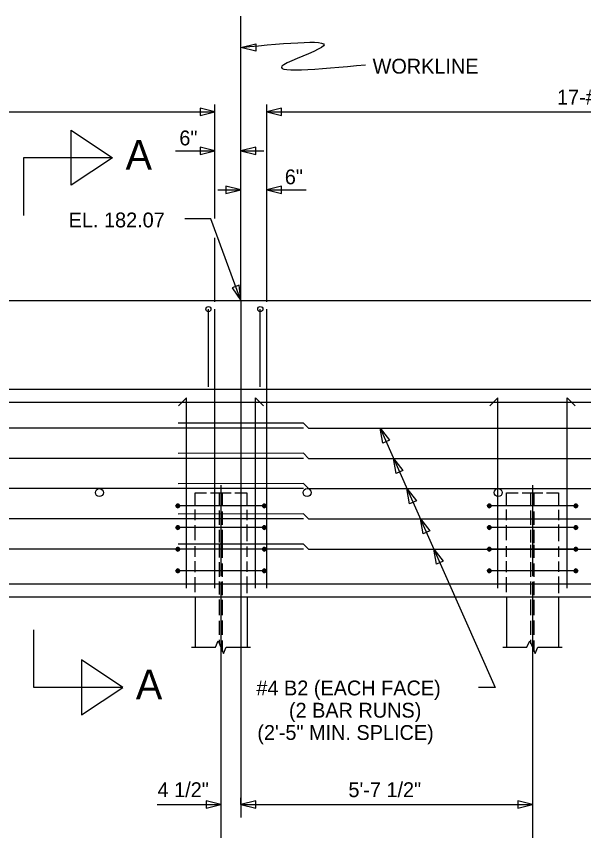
# Model space of a CAD drawing. Extents: x -41 to 191, y -168 to 6.
# Drawn here: x 143.62 to 154.55, y -40.75 to -25.07 of the extents above; entities that cross this region are included whole.
import ezdxf

# ---------------------------------------------------------------- set-up
doc = ezdxf.new("R2010")
doc.units = 0
for name, color, linetype in [('Arrowhead Terminators CELL', 7, 'Continuous'), ('Dimension Lines', 7, 'Continuous'), ('Mis -L- Lines', 7, 'Continuous'), ('Mis Object Lines', 7, 'Continuous'), ('Rebar Lines', 7, 'Continuous'), ('Rebar Lines CELL', 7, 'Continuous'), ('Text', 7, 'Continuous'), ('Title Text', 7, 'Continuous')]:
    doc.layers.add(name, color=color, linetype=linetype)

msp = doc.modelspace()

# ---------------------------------------------------------------- linework, layer by layer
at = {"layer": 'Arrowhead Terminators CELL'}
for points in [[(147.948, -25.666), (148.234, -25.594), (148.234, -25.737)], [(147.448, -26.909), (147.162, -26.837), (147.162, -26.98)], [(148.448, -26.909), (148.734, -26.98), (148.734, -26.837)], [(145.476, -27.792), (144.682, -28.321), (144.682, -27.263)], [(147.448, -27.659), (147.162, -27.587), (147.162, -27.73)], [(147.948, -27.659), (148.234, -27.73), (148.234, -27.587)], [(147.948, -28.409), (147.662, -28.337), (147.662, -28.48)], [(148.448, -28.409), (148.734, -28.48), (148.734, -28.337)], [(147.948, -30.54), (147.916, -30.247), (147.782, -30.296)], [(150.629, -32.999), (150.811, -33.231), (150.68, -33.289)], [(150.888, -33.582), (151.07, -33.815), (150.939, -33.873)], [(151.147, -34.165), (151.329, -34.398), (151.198, -34.456)], [(151.406, -34.749), (151.588, -34.981), (151.457, -35.039)], [(151.665, -35.332), (151.847, -35.564), (151.716, -35.623)], [(145.674, -37.994), (144.881, -37.465), (144.881, -38.523)], [(147.566, -40.249), (147.28, -40.177), (147.28, -40.32)], [(147.948, -40.249), (148.234, -40.32), (148.234, -40.177)], [(153.566, -40.249), (153.28, -40.177), (153.28, -40.32)]]:
    msp.add_lwpolyline(points, close=True, dxfattribs=at)
at = {"layer": 'Dimension Lines'}
for p, q in [((147.448, -28.959), (147.448, -26.766)), ((148.448, -30.564), (148.448, -26.766)), ((131.375, -26.909), (147.448, -26.909)), ((148.448, -26.909), (164.521, -26.909)), ((149.531, -26.909), (164.551, -26.909)), ((146.693, -27.659), (147.448, -27.659)), ((147.948, -27.659), (148.394, -27.659)), ((147.502, -28.409), (147.948, -28.409)), ((148.448, -28.409), (149.203, -28.409)), ((147.448, -30.564), (147.448, -29.336)), ((147.566, -36.249), (147.566, -42.558)), ((153.566, -36.249), (153.566, -42.558)), ((147.948, -40.249), (147.948, -40.124)), ((146.34, -40.249), (147.566, -40.249)), ((147.948, -40.249), (153.566, -40.249))]:
    msp.add_line(p, q, dxfattribs=at)
for points in [[(145.476, -27.792), (143.764, -27.792), (143.764, -28.903)], [(147.948, -30.54), (147.371, -28.97), (146.871, -28.97)], [(150.629, -32.999), (152.847, -37.993), (152.527, -37.993)], [(145.674, -37.994), (143.963, -37.994), (143.963, -36.883)]]:
    msp.add_lwpolyline(points, dxfattribs=at)
msp.add_spline([(147.948, -25.666), (149.503, -25.666), (148.777, -25.999), (150.346, -25.999)], degree=3, dxfattribs=at)
at = {"layer": 'Mis -L- Lines'}
for q in [(147.948, -25.066), (147.948, -40.499)]:
    msp.add_line((147.948, -30.54), q, dxfattribs=at)
at = {"layer": 'Mis Object Lines'}
for p, q in [((137.623, -30.54), (164.491, -30.54)), ((131.167, -32.249), (147.948, -32.249)), ((147.948, -32.249), (168.185, -32.249)), ((133.764, -36.249), (168.185, -36.249))]:
    msp.add_line(p, q, dxfattribs=at)
at = {"layer": 'Rebar Lines'}
for p, q in [((147.323, -32.207), (147.323, -30.707)), ((147.448, -36.082), (147.448, -30.707)), ((148.323, -32.207), (148.323, -30.707)), ((148.448, -36.082), (148.448, -30.707)), ((146.9, -32.415), (146.746, -32.569)), ((146.9, -36.082), (146.9, -32.415)), ((148.233, -32.415), (148.387, -32.569)), ((148.233, -36.082), (148.233, -32.415)), ((152.9, -32.415), (152.746, -32.569)), ((152.9, -36.082), (152.9, -32.415)), ((154.233, -32.415), (154.387, -32.569)), ((154.233, -36.082), (154.233, -32.415)), ((127.69, -32.5), (166.732, -32.5)), ((149.156, -32.902), (146.74, -32.904)), ((149.253, -32.999), (149.156, -32.902)), ((149.156, -32.999), (127.115, -32.999)), ((149.253, -32.999), (167.24, -32.999)), ((149.156, -33.485), (146.74, -33.487)), ((149.253, -33.582), (149.156, -33.485)), ((149.156, -33.582), (127.115, -33.582)), ((149.253, -33.582), (167.24, -33.582)), ((149.156, -34.165), (127.115, -34.165)), ((149.156, -34.069), (146.74, -34.07)), ((147.566, -34.097), (147.566, -35.854)), ((149.253, -34.165), (149.156, -34.069)), ((149.253, -34.165), (167.24, -34.165)), ((153.566, -34.097), (153.566, -35.854)), ((147.535, -34.491), (147.535, -34.249)), ((147.598, -34.497), (147.598, -34.249)), ((153.535, -34.491), (153.535, -34.249)), ((153.598, -34.497), (153.598, -34.249)), ((149.156, -34.652), (146.74, -34.654)), ((147.535, -34.863), (147.535, -34.584)), ((147.598, -34.863), (147.598, -34.607)), ((149.253, -34.749), (149.156, -34.652)), ((153.535, -34.863), (153.535, -34.584)), ((153.598, -34.863), (153.598, -34.607)), ((149.156, -34.749), (127.115, -34.749)), ((149.253, -34.749), (167.24, -34.749)), ((147.535, -35.206), (147.535, -34.956)), ((147.598, -35.217), (147.598, -34.956)), ((153.535, -35.206), (153.535, -34.956)), ((153.598, -35.217), (153.598, -34.956)), ((149.156, -35.235), (146.74, -35.237)), ((147.535, -35.491), (147.535, -35.249)), ((147.598, -35.497), (147.598, -35.249)), ((149.253, -35.332), (149.156, -35.235)), ((153.535, -35.491), (153.535, -35.249)), ((153.598, -35.497), (153.598, -35.249)), ((149.156, -35.332), (127.115, -35.332)), ((149.253, -35.332), (167.24, -35.332)), ((147.535, -35.863), (147.535, -35.584)), ((147.598, -35.863), (147.598, -35.607)), ((153.535, -35.863), (153.535, -35.584)), ((153.598, -35.863), (153.598, -35.607)), ((127.69, -35.999), (166.825, -35.999)), ((147.535, -36.206), (147.535, -35.956)), ((147.566, -35.958), (147.566, -36.249)), ((147.598, -36.217), (147.598, -35.956)), ((153.535, -36.206), (153.535, -35.956)), ((153.566, -35.958), (153.566, -36.249)), ((153.598, -36.217), (153.598, -35.956)), ((147.066, -36.266), (147.066, -37.218)), ((147.535, -36.601), (147.535, -36.304)), ((147.566, -36.318), (147.566, -37.524)), ((147.598, -36.601), (147.598, -36.31)), ((148.067, -36.266), (148.067, -37.218)), ((153.066, -36.266), (153.066, -37.218)), ((153.535, -36.601), (153.535, -36.304)), ((153.566, -36.318), (153.566, -37.524)), ((153.598, -36.601), (153.598, -36.31)), ((154.067, -36.266), (154.067, -37.218)), ((147.598, -36.984), (147.598, -36.705)), ((153.598, -36.984), (153.598, -36.705)), ((147.535, -36.984), (147.535, -36.711)), ((153.535, -36.984), (153.535, -36.711)), ((147.535, -37.152), (147.535, -37.077)), ((147.598, -37.301), (147.598, -37.089)), ((153.535, -37.152), (153.535, -37.077)), ((153.598, -37.301), (153.598, -37.089))]:
    msp.add_line(p, q, dxfattribs=at)
for points in [[(147.066, -34.482), (147.066, -34.249), (147.289, -34.249)], [(147.364, -34.249), (147.764, -34.249)], [(147.833, -34.249), (148.066, -34.249), (148.066, -34.495)], [(153.066, -34.482), (153.066, -34.249), (153.289, -34.249)], [(153.364, -34.249), (153.764, -34.249)], [(153.833, -34.249), (154.066, -34.249), (154.066, -34.495)], [(147.066, -34.773), (147.066, -34.565)], [(148.066, -34.571), (148.066, -34.77)], [(153.066, -34.773), (153.066, -34.565)], [(154.066, -34.571), (154.066, -34.77)], [(147.066, -35.16), (147.066, -34.868)], [(148.066, -34.855), (148.066, -35.176)], [(153.066, -35.16), (153.066, -34.868)], [(154.066, -34.855), (154.066, -35.176)], [(147.066, -35.482), (147.066, -35.274)], [(148.066, -35.28), (148.066, -35.479)], [(153.066, -35.482), (153.066, -35.274)], [(154.066, -35.28), (154.066, -35.479)], [(147.066, -35.773), (147.066, -35.565)], [(148.066, -35.571), (148.066, -35.77)], [(153.066, -35.773), (153.066, -35.565)], [(154.066, -35.571), (154.066, -35.77)], [(147.066, -36.16), (147.066, -35.868)], [(148.066, -35.855), (148.066, -36.176)], [(153.066, -36.16), (153.066, -35.868)], [(154.066, -35.855), (154.066, -36.176)], [(146.996, -37.218), (147.458, -37.218), (147.513, -37.098), (147.615, -37.343), (147.667, -37.218), (148.133, -37.218)], [(152.996, -37.218), (153.458, -37.218), (153.513, -37.098), (153.615, -37.343), (153.667, -37.218), (154.133, -37.218)]]:
    msp.add_lwpolyline(points, dxfattribs=at)
for centre in [(147.323, -30.707), (148.323, -30.707)]:
    msp.add_circle(centre, 0.0495, dxfattribs=at)
at = {"layer": 'Rebar Lines CELL'}
for p, q in [((148.4, -34.499), (146.733, -34.499)), ((154.4, -34.499), (152.733, -34.499)), ((148.4, -34.915), (146.733, -34.915)), ((154.4, -34.915), (152.733, -34.915)), ((148.4, -35.332), (146.733, -35.332)), ((154.4, -35.332), (152.733, -35.332)), ((148.4, -35.749), (146.733, -35.749)), ((154.4, -35.749), (152.733, -35.749))]:
    msp.add_line(p, q, dxfattribs=at)
for points in [[(146.733, -34.463), (146.72, -34.466), (146.708, -34.474), (146.7, -34.485), (146.698, -34.499), (146.7, -34.512), (146.708, -34.523), (146.72, -34.531), (146.733, -34.534), (146.746, -34.531), (146.758, -34.523), (146.766, -34.512), (146.768, -34.499), (146.766, -34.485), (146.758, -34.474), (146.747, -34.466), (146.733, -34.463), (146.733, -34.499), (146.733, -34.534), (146.72, -34.531), (146.733, -34.499), (146.708, -34.523), (146.7, -34.512), (146.733, -34.499), (146.698, -34.499), (146.7, -34.485), (146.733, -34.499), (146.708, -34.474), (146.72, -34.466), (146.733, -34.499), (146.747, -34.466), (146.758, -34.474), (146.733, -34.499), (146.766, -34.485), (146.768, -34.499), (146.733, -34.499), (146.766, -34.512), (146.758, -34.523), (146.733, -34.499), (146.746, -34.531)], [(148.4, -34.463), (148.386, -34.466), (148.375, -34.474), (148.367, -34.485), (148.365, -34.499), (148.367, -34.512), (148.375, -34.523), (148.386, -34.531), (148.4, -34.534), (148.413, -34.531), (148.425, -34.523), (148.432, -34.512), (148.435, -34.499), (148.432, -34.485), (148.425, -34.474), (148.413, -34.466), (148.4, -34.463), (148.4, -34.499), (148.4, -34.534), (148.386, -34.531), (148.4, -34.499), (148.375, -34.523), (148.367, -34.512), (148.4, -34.499), (148.365, -34.499), (148.367, -34.485), (148.4, -34.499), (148.375, -34.474), (148.386, -34.466), (148.4, -34.499), (148.413, -34.466), (148.425, -34.474), (148.4, -34.499), (148.432, -34.485), (148.435, -34.499), (148.4, -34.499), (148.432, -34.512), (148.425, -34.523), (148.4, -34.499), (148.413, -34.531)], [(152.733, -34.463), (152.72, -34.466), (152.708, -34.474), (152.7, -34.485), (152.698, -34.499), (152.7, -34.512), (152.708, -34.523), (152.72, -34.531), (152.733, -34.534), (152.746, -34.531), (152.758, -34.523), (152.766, -34.512), (152.768, -34.499), (152.766, -34.485), (152.758, -34.474), (152.747, -34.466), (152.733, -34.463), (152.733, -34.499), (152.733, -34.534), (152.72, -34.531), (152.733, -34.499), (152.708, -34.523), (152.7, -34.512), (152.733, -34.499), (152.698, -34.499), (152.7, -34.485), (152.733, -34.499), (152.708, -34.474), (152.72, -34.466), (152.733, -34.499), (152.747, -34.466), (152.758, -34.474), (152.733, -34.499), (152.766, -34.485), (152.768, -34.499), (152.733, -34.499), (152.766, -34.512), (152.758, -34.523), (152.733, -34.499), (152.746, -34.531)], [(154.4, -34.463), (154.386, -34.466), (154.375, -34.474), (154.367, -34.485), (154.365, -34.499), (154.367, -34.512), (154.375, -34.523), (154.386, -34.531), (154.4, -34.534), (154.413, -34.531), (154.425, -34.523), (154.432, -34.512), (154.435, -34.499), (154.432, -34.485), (154.425, -34.474), (154.413, -34.466), (154.4, -34.463), (154.4, -34.499), (154.4, -34.534), (154.386, -34.531), (154.4, -34.499), (154.375, -34.523), (154.367, -34.512), (154.4, -34.499), (154.365, -34.499), (154.367, -34.485), (154.4, -34.499), (154.375, -34.474), (154.386, -34.466), (154.4, -34.499), (154.413, -34.466), (154.425, -34.474), (154.4, -34.499), (154.432, -34.485), (154.435, -34.499), (154.4, -34.499), (154.432, -34.512), (154.425, -34.523), (154.4, -34.499), (154.413, -34.531)], [(146.733, -34.88), (146.72, -34.883), (146.708, -34.89), (146.7, -34.902), (146.698, -34.915), (146.7, -34.929), (146.708, -34.94), (146.72, -34.948), (146.733, -34.95), (146.746, -34.948), (146.758, -34.94), (146.766, -34.929), (146.768, -34.915), (146.766, -34.902), (146.758, -34.89), (146.747, -34.883), (146.733, -34.88), (146.733, -34.915), (146.733, -34.95), (146.72, -34.948), (146.733, -34.915), (146.708, -34.94), (146.7, -34.929), (146.733, -34.915), (146.698, -34.915), (146.7, -34.902), (146.733, -34.915), (146.708, -34.89), (146.72, -34.883), (146.733, -34.915), (146.747, -34.883), (146.758, -34.89), (146.733, -34.915), (146.766, -34.902), (146.768, -34.915), (146.733, -34.915), (146.766, -34.929), (146.758, -34.94), (146.733, -34.915), (146.746, -34.948)], [(148.4, -34.88), (148.386, -34.883), (148.375, -34.89), (148.367, -34.902), (148.365, -34.915), (148.367, -34.929), (148.375, -34.94), (148.386, -34.948), (148.4, -34.95), (148.413, -34.948), (148.425, -34.94), (148.432, -34.929), (148.435, -34.915), (148.432, -34.902), (148.425, -34.89), (148.413, -34.883), (148.4, -34.88), (148.4, -34.915), (148.4, -34.95), (148.386, -34.948), (148.4, -34.915), (148.375, -34.94), (148.367, -34.929), (148.4, -34.915), (148.365, -34.915), (148.367, -34.902), (148.4, -34.915), (148.375, -34.89), (148.386, -34.883), (148.4, -34.915), (148.413, -34.883), (148.425, -34.89), (148.4, -34.915), (148.432, -34.902), (148.435, -34.915), (148.4, -34.915), (148.432, -34.929), (148.425, -34.94), (148.4, -34.915), (148.413, -34.948)], [(152.733, -34.88), (152.72, -34.883), (152.708, -34.89), (152.7, -34.902), (152.698, -34.915), (152.7, -34.929), (152.708, -34.94), (152.72, -34.948), (152.733, -34.95), (152.746, -34.948), (152.758, -34.94), (152.766, -34.929), (152.768, -34.915), (152.766, -34.902), (152.758, -34.89), (152.747, -34.883), (152.733, -34.88), (152.733, -34.915), (152.733, -34.95), (152.72, -34.948), (152.733, -34.915), (152.708, -34.94), (152.7, -34.929), (152.733, -34.915), (152.698, -34.915), (152.7, -34.902), (152.733, -34.915), (152.708, -34.89), (152.72, -34.883), (152.733, -34.915), (152.747, -34.883), (152.758, -34.89), (152.733, -34.915), (152.766, -34.902), (152.768, -34.915), (152.733, -34.915), (152.766, -34.929), (152.758, -34.94), (152.733, -34.915), (152.746, -34.948)], [(154.4, -34.88), (154.386, -34.883), (154.375, -34.89), (154.367, -34.902), (154.365, -34.915), (154.367, -34.929), (154.375, -34.94), (154.386, -34.948), (154.4, -34.95), (154.413, -34.948), (154.425, -34.94), (154.432, -34.929), (154.435, -34.915), (154.432, -34.902), (154.425, -34.89), (154.413, -34.883), (154.4, -34.88), (154.4, -34.915), (154.4, -34.95), (154.386, -34.948), (154.4, -34.915), (154.375, -34.94), (154.367, -34.929), (154.4, -34.915), (154.365, -34.915), (154.367, -34.902), (154.4, -34.915), (154.375, -34.89), (154.386, -34.883), (154.4, -34.915), (154.413, -34.883), (154.425, -34.89), (154.4, -34.915), (154.432, -34.902), (154.435, -34.915), (154.4, -34.915), (154.432, -34.929), (154.425, -34.94), (154.4, -34.915), (154.413, -34.948)], [(146.733, -35.297), (146.72, -35.299), (146.708, -35.307), (146.7, -35.318), (146.698, -35.332), (146.7, -35.345), (146.708, -35.357), (146.72, -35.364), (146.733, -35.367), (146.746, -35.364), (146.758, -35.357), (146.766, -35.345), (146.768, -35.332), (146.766, -35.318), (146.758, -35.307), (146.747, -35.299), (146.733, -35.297), (146.733, -35.332), (146.733, -35.367), (146.72, -35.364), (146.733, -35.332), (146.708, -35.357), (146.7, -35.345), (146.733, -35.332), (146.698, -35.332), (146.7, -35.318), (146.733, -35.332), (146.708, -35.307), (146.72, -35.299), (146.733, -35.332), (146.747, -35.299), (146.758, -35.307), (146.733, -35.332), (146.766, -35.318), (146.768, -35.332), (146.733, -35.332), (146.766, -35.345), (146.758, -35.357), (146.733, -35.332), (146.746, -35.364)], [(148.4, -35.297), (148.386, -35.299), (148.375, -35.307), (148.367, -35.318), (148.365, -35.332), (148.367, -35.345), (148.375, -35.357), (148.386, -35.364), (148.4, -35.367), (148.413, -35.364), (148.425, -35.357), (148.432, -35.345), (148.435, -35.332), (148.432, -35.318), (148.425, -35.307), (148.413, -35.299), (148.4, -35.297), (148.4, -35.332), (148.4, -35.367), (148.386, -35.364), (148.4, -35.332), (148.375, -35.357), (148.367, -35.345), (148.4, -35.332), (148.365, -35.332), (148.367, -35.318), (148.4, -35.332), (148.375, -35.307), (148.386, -35.299), (148.4, -35.332), (148.413, -35.299), (148.425, -35.307), (148.4, -35.332), (148.432, -35.318), (148.435, -35.332), (148.4, -35.332), (148.432, -35.345), (148.425, -35.357), (148.4, -35.332), (148.413, -35.364)], [(152.733, -35.297), (152.72, -35.299), (152.708, -35.307), (152.7, -35.318), (152.698, -35.332), (152.7, -35.345), (152.708, -35.357), (152.72, -35.364), (152.733, -35.367), (152.746, -35.364), (152.758, -35.357), (152.766, -35.345), (152.768, -35.332), (152.766, -35.318), (152.758, -35.307), (152.747, -35.299), (152.733, -35.297), (152.733, -35.332), (152.733, -35.367), (152.72, -35.364), (152.733, -35.332), (152.708, -35.357), (152.7, -35.345), (152.733, -35.332), (152.698, -35.332), (152.7, -35.318), (152.733, -35.332), (152.708, -35.307), (152.72, -35.299), (152.733, -35.332), (152.747, -35.299), (152.758, -35.307), (152.733, -35.332), (152.766, -35.318), (152.768, -35.332), (152.733, -35.332), (152.766, -35.345), (152.758, -35.357), (152.733, -35.332), (152.746, -35.364)], [(154.4, -35.297), (154.386, -35.299), (154.375, -35.307), (154.367, -35.318), (154.365, -35.332), (154.367, -35.345), (154.375, -35.357), (154.386, -35.364), (154.4, -35.367), (154.413, -35.364), (154.425, -35.357), (154.432, -35.345), (154.435, -35.332), (154.432, -35.318), (154.425, -35.307), (154.413, -35.299), (154.4, -35.297), (154.4, -35.332), (154.4, -35.367), (154.386, -35.364), (154.4, -35.332), (154.375, -35.357), (154.367, -35.345), (154.4, -35.332), (154.365, -35.332), (154.367, -35.318), (154.4, -35.332), (154.375, -35.307), (154.386, -35.299), (154.4, -35.332), (154.413, -35.299), (154.425, -35.307), (154.4, -35.332), (154.432, -35.318), (154.435, -35.332), (154.4, -35.332), (154.432, -35.345), (154.425, -35.357), (154.4, -35.332), (154.413, -35.364)], [(146.733, -35.713), (146.72, -35.716), (146.708, -35.724), (146.7, -35.735), (146.698, -35.749), (146.7, -35.762), (146.708, -35.773), (146.72, -35.781), (146.733, -35.784), (146.746, -35.781), (146.758, -35.773), (146.766, -35.762), (146.768, -35.749), (146.766, -35.735), (146.758, -35.724), (146.747, -35.716), (146.733, -35.713), (146.733, -35.749), (146.733, -35.784), (146.72, -35.781), (146.733, -35.749), (146.708, -35.773), (146.7, -35.762), (146.733, -35.749), (146.698, -35.749), (146.7, -35.735), (146.733, -35.749), (146.708, -35.724), (146.72, -35.716), (146.733, -35.749), (146.747, -35.716), (146.758, -35.724), (146.733, -35.749), (146.766, -35.735), (146.768, -35.749), (146.733, -35.749), (146.766, -35.762), (146.758, -35.773), (146.733, -35.749), (146.746, -35.781)], [(148.4, -35.713), (148.386, -35.716), (148.375, -35.724), (148.367, -35.735), (148.365, -35.749), (148.367, -35.762), (148.375, -35.773), (148.386, -35.781), (148.4, -35.784), (148.413, -35.781), (148.425, -35.773), (148.432, -35.762), (148.435, -35.749), (148.432, -35.735), (148.425, -35.724), (148.413, -35.716), (148.4, -35.713), (148.4, -35.749), (148.4, -35.784), (148.386, -35.781), (148.4, -35.749), (148.375, -35.773), (148.367, -35.762), (148.4, -35.749), (148.365, -35.749), (148.367, -35.735), (148.4, -35.749), (148.375, -35.724), (148.386, -35.716), (148.4, -35.749), (148.413, -35.716), (148.425, -35.724), (148.4, -35.749), (148.432, -35.735), (148.435, -35.749), (148.4, -35.749), (148.432, -35.762), (148.425, -35.773), (148.4, -35.749), (148.413, -35.781)], [(152.733, -35.713), (152.72, -35.716), (152.708, -35.724), (152.7, -35.735), (152.698, -35.749), (152.7, -35.762), (152.708, -35.773), (152.72, -35.781), (152.733, -35.784), (152.746, -35.781), (152.758, -35.773), (152.766, -35.762), (152.768, -35.749), (152.766, -35.735), (152.758, -35.724), (152.747, -35.716), (152.733, -35.713), (152.733, -35.749), (152.733, -35.784), (152.72, -35.781), (152.733, -35.749), (152.708, -35.773), (152.7, -35.762), (152.733, -35.749), (152.698, -35.749), (152.7, -35.735), (152.733, -35.749), (152.708, -35.724), (152.72, -35.716), (152.733, -35.749), (152.747, -35.716), (152.758, -35.724), (152.733, -35.749), (152.766, -35.735), (152.768, -35.749), (152.733, -35.749), (152.766, -35.762), (152.758, -35.773), (152.733, -35.749), (152.746, -35.781)], [(154.4, -35.713), (154.386, -35.716), (154.375, -35.724), (154.367, -35.735), (154.365, -35.749), (154.367, -35.762), (154.375, -35.773), (154.386, -35.781), (154.4, -35.784), (154.413, -35.781), (154.425, -35.773), (154.432, -35.762), (154.435, -35.749), (154.432, -35.735), (154.425, -35.724), (154.413, -35.716), (154.4, -35.713), (154.4, -35.749), (154.4, -35.784), (154.386, -35.781), (154.4, -35.749), (154.375, -35.773), (154.367, -35.762), (154.4, -35.749), (154.365, -35.749), (154.367, -35.735), (154.4, -35.749), (154.375, -35.724), (154.386, -35.716), (154.4, -35.749), (154.413, -35.716), (154.425, -35.724), (154.4, -35.749), (154.432, -35.735), (154.435, -35.749), (154.4, -35.749), (154.432, -35.762), (154.425, -35.773), (154.4, -35.749), (154.413, -35.781)]]:
    msp.add_lwpolyline(points, dxfattribs=at)
for centre in [(145.225, -34.242), (149.225, -34.242), (152.904, -34.242)]:
    msp.add_circle(centre, 0.0773, dxfattribs=at)

# ---------------------------------------------------------------- texts
at = {"layer": 'Text'}
for s, p in [('WORKLINE', (150.486, -26.171)), ('17-#4 V2 @ 1\'-0" CTS. (EA. FACE)', (154.037, -26.766)), ('6"', (146.764, -27.553)), ('6"', (148.795, -28.303)), ('EL. 182.07', (144.633, -29.133)), ('#4 B2 (EACH FACE)', (148.248, -38.148)), ('(2 BAR RUNS)', (148.874, -38.577)), ('(2\'-5" MIN. SPLICE)', (148.266, -39.006)), ('4 1/2"', (146.345, -40.108)), ('5\'-7 1/2"', (150.02, -40.108))]:
    msp.add_text(s, height=0.286, dxfattribs=at).set_placement(p)
at = {"layer": 'Title Text'}
for p in [(145.728, -28.023), (145.926, -38.225)]:
    msp.add_text('A', height=0.572, rotation=360, dxfattribs=at).set_placement(p)

doc.saveas('drawing.dxf')
